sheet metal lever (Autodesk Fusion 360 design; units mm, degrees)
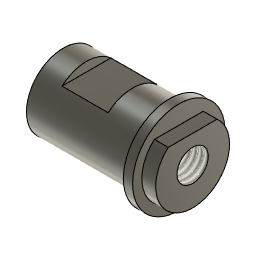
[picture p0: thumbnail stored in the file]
sketch "Sketch1" plane through (0, 0, 0) normal (1, 0, 0) x axis (0, 1, 0)
  line L1 (5.2915, 6) -> (-5.2915, 6)
  circle C1 centre (0, 0) radius 8
  circle C2 centre (0, 0) radius 10
  point P1 (0, 0)
  point P2 (0, 0)
  point P3 (-5.2915, 6)
  point P4 (5.2915, 6)
  coincident P1 P2
  coincident C1 P3
  coincident C1 P4
  horizontal L1
  concentric C1 C2
  dimension "d1" diameter C1 = 16
  dimension "d2" distance P1 L1 = 6
  dimension "d10" diameter C2 = 20
extrude "Extrude1" new body sketch "Sketch1" profile of C1 L1 against normal blind 25
extrude "Extrude2" add sketch "Sketch1" profile of C1 L1 along normal blind 3
hole "Hole1" HoleDepth 10 HoleDiameter 6.78 TipAngle 180
extrude "Extrude3" add sketch "Sketch1" profile of C1 C2 against normal blind 2
extrude "Extrude4" cut sketch "Sketch1" profile of C1 L1 blind -10 from offset -10
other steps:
thread "Thread1"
